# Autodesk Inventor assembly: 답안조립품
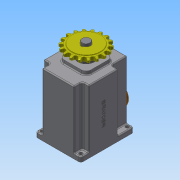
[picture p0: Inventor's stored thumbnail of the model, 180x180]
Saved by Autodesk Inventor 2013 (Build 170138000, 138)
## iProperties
Created: 2017-12
Part Number: 답안조립품
Document SubType Name: Assembly
Designer: Administrator
Mass: 2741.19 g
Surface Area: 2015.58 cm^2
Volume: 734.134 cm^3
Density: 3.73392 g/cm^3
Author: Administrator
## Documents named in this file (17)
- C:\Users\Administrator\Desktop\371208V1026\답안조립품.iam
- C:\Users\Administrator\Desktop\371208V1026\가변스프링.ipt
- C:\Users\Administrator\Desktop\371208V1026\멈춤나사 M3x8.ipt
- C:\Users\Administrator\Desktop\371208V1026\메인축.ipt
- C:\Users\Administrator\Desktop\371208V1026\베어링 608.ipt
- C:\Users\Administrator\Desktop\371208V1026\베어링 6003.ipt
- C:\Users\Administrator\Desktop\371208V1026\본체.ipt
- C:\Users\Administrator\Desktop\371208V1026\볼트 M4 x 10.ipt
- C:\Users\Administrator\Desktop\371208V1026\부시.ipt
- C:\Users\Administrator\Desktop\371208V1026\상부 캡.ipt
- C:\Users\Administrator\Desktop\371208V1026\서브축.ipt
- C:\Users\Administrator\Desktop\371208V1026\스프로킷.ipt
- C:\Users\Administrator\Desktop\371208V1026\슬라이더.ipt
- C:\Users\Administrator\Desktop\371208V1026\오일 실 8 22 7.ipt
- C:\Users\Administrator\Desktop\371208V1026\오일 실 17 32 8.ipt
- C:\Users\Administrator\Desktop\371208V1026\커버.ipt
- C:\Users\Administrator\Desktop\371208V1026\키 5 x 5 x 18.ipt
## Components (1 placed, 1 different names)
1. 가변스프링:1
